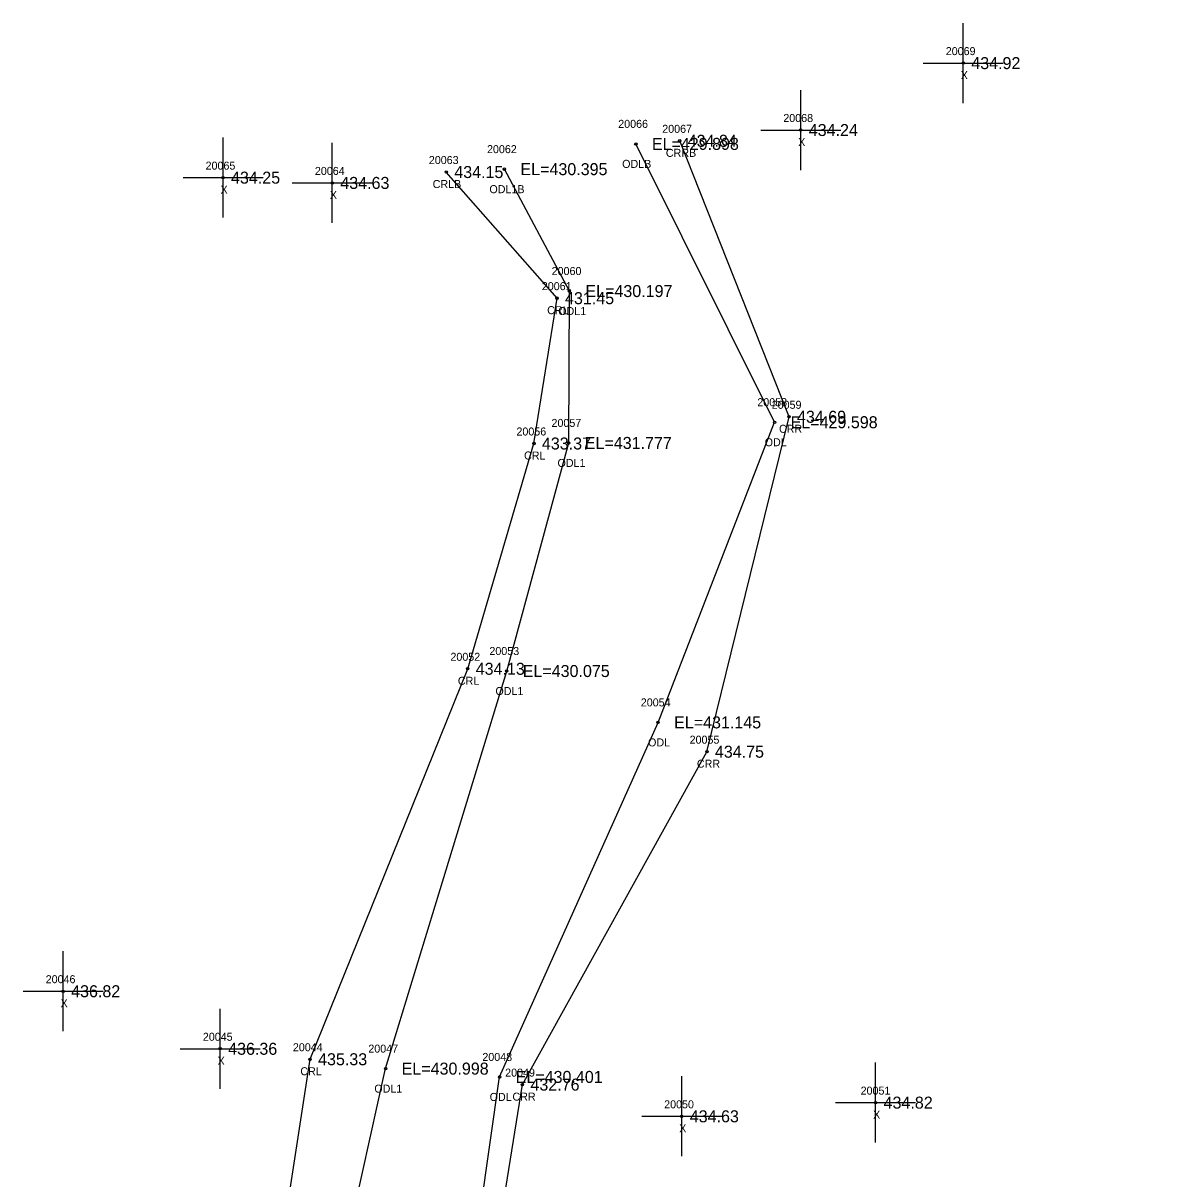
# Model space of a CAD drawing. Extents: x 1810114 to 1811498, y 790790 to 791824.
# Drawn here: x 1810690.3 to 1810832.5, y 791679.6 to 791824 of the extents above; entities that cross this region are included whole.
import ezdxf

# ---------------------------------------------------------------- set-up
doc = ezdxf.new("R2010")
doc.units = 0
for name, color, linetype in [('RD_EX_H2O', 7, 'Continuous'), ('RD_EX_H2O_txCode', 7, 'Continuous'), ('RD_EX_Misc', 7, 'Continuous'), ('RD_EX_Misc_txCode', 7, 'Continuous'), ('RD_EX_TX_H2O_ELEV', 7, 'Continuous'), ('RD_EX_TX_Misc_ELEV', 7, 'Continuous'), ('RD_SMD_Locator', 7, 'Continuous')]:
    doc.layers.add(name, color=color, linetype=linetype)

msp = doc.modelspace()

# ---------------------------------------------------------------- linework, layer by layer
at = {"layer": 'RD_EX_H2O'}
for points in [[(1810794.5, 791298.9), (1810828.59, 791424.04), (1810821.51, 791432.91), (1810774.54, 791452.98), (1810741.95, 791465.37), (1810743.78, 791497), (1810736.7, 791599.78), (1810749.88, 791692.36), (1810769.68, 791736.66), (1810784.24, 791774.17), (1810766.9, 791808.95)], [(1810797.71, 791296.87), (1810832.51, 791426.19), (1810824.93, 791438.48), (1810774.65, 791454.91), (1810754.82, 791471.31), (1810756.82, 791503.13), (1810738.07, 791600.2), (1810752.73, 791691.4), (1810775.78, 791733), (1810786.04, 791774.85), (1810772.38, 791809.33)], [(1810783.58, 791301.54), (1810809.42, 791415.43), (1810809.03, 791421.06), (1810765.94, 791440.4), (1810731.85, 791461.34), (1810727.54, 791486.73), (1810720.53, 791597.07), (1810716.45, 791606.79), (1810735.63, 791693.4), (1810750.76, 791743.08), (1810758.52, 791771.58), (1810758.6, 791790.56), (1810750.48, 791805.79)], [(1810781.61, 791303.43), (1810807.2, 791415.78), (1810808.22, 791420.49), (1810765.69, 791434.41), (1810731.68, 791459.26), (1810725.69, 791486.37), (1810718.09, 791596.36), (1810712.45, 791605.3), (1810726.19, 791694.57), (1810745.89, 791743.36), (1810754.16, 791771.51), (1810757.05, 791789.67), (1810743.21, 791805.43)]]:
    msp.add_lwpolyline(points, dxfattribs=at)
at = {"layer": 'RD_EX_Misc'}
for p, q in [((1810807.82, 791814.04), (1810807.82, 791824.04)), ((1810802.82, 791819.04), (1810812.82, 791819.04)), ((1810787.51, 791805.68), (1810787.51, 791815.68)), ((1810782.51, 791810.68), (1810792.51, 791810.68)), ((1810715.31, 791799.73), (1810715.31, 791809.73)), ((1810728.97, 791799.07), (1810728.97, 791809.07)), ((1810710.31, 791804.73), (1810720.31, 791804.73)), ((1810723.97, 791804.07), (1810733.97, 791804.07)), ((1810695.33, 791698.07), (1810695.33, 791708.07)), ((1810690.33, 791703.07), (1810700.33, 791703.07)), ((1810714.95, 791690.88), (1810714.95, 791700.88)), ((1810709.95, 791695.88), (1810719.95, 791695.88)), ((1810796.86, 791684.15), (1810796.86, 791694.15)), ((1810772.64, 791682.44), (1810772.64, 791692.44)), ((1810791.86, 791689.15), (1810801.86, 791689.15)), ((1810767.64, 791687.44), (1810777.64, 791687.44))]:
    msp.add_line(p, q, dxfattribs=at)
at = {"layer": 'RD_SMD_Locator'}
for centre in [(1810807.82, 791819.04), (1810787.51, 791810.68), (1810766.9, 791808.95), (1810772.38, 791809.33), (1810743.21, 791805.43), (1810750.48, 791805.79), (1810715.31, 791804.73), (1810728.97, 791804.07), (1810757.05, 791789.67), (1810758.6, 791790.56), (1810784.24, 791774.17), (1810786.04, 791774.85), (1810754.16, 791771.51), (1810758.52, 791771.58), (1810745.89, 791743.36), (1810750.76, 791743.08), (1810769.68, 791736.66), (1810775.78, 791733), (1810695.33, 791703.07), (1810714.95, 791695.88), (1810726.19, 791694.57), (1810735.63, 791693.4), (1810749.88, 791692.36), (1810752.73, 791691.4), (1810796.86, 791689.15), (1810772.64, 791687.44)]:
    msp.add_circle(centre, 0.15, dxfattribs=at)

# ---------------------------------------------------------------- texts
at = {"layer": 'RD_EX_H2O_txCode'}
for s, p in [('20066', (1810764.7, 791810.95)), ('20067', (1810770.2, 791810.33)), ('20062', (1810748.3, 791807.79)), ('CRRB', (1810770.65, 791807.33)), ('20063', (1810741.03, 791806.43)), ('ODLB', (1810765.19, 791805.95)), ('CRLB', (1810741.51, 791803.43)), ('ODL1B', (1810748.6, 791802.79)), ('20060', (1810756.38, 791792.56)), ('20061', (1810755.15, 791790.67)), ('CRL', (1810755.82, 791787.67)), ('ODL1', (1810757.2, 791787.56)), ('20058', (1810782.08, 791776.17)), ('20059', (1810783.88, 791775.85)), ('20057', (1810756.36, 791773.58)), ('CRR', (1810784.79, 791772.85)), ('20056', (1810751.98, 791772.51)), ('ODL', (1810783, 791771.17)), ('CRL', (1810752.93, 791769.51)), ('ODL1', (1810757.11, 791768.58)), ('20052', (1810743.73, 791744.36)), ('20053', (1810748.6, 791745.08)), ('CRL', (1810744.66, 791741.36)), ('ODL1', (1810749.35, 791740.08)), ('20054', (1810767.52, 791738.66)), ('ODL', (1810768.43, 791733.66)), ('20055', (1810773.62, 791734)), ('CRR', (1810774.53, 791731)), ('20044', (1810724.04, 791695.57)), ('20047', (1810733.47, 791695.4)), ('20048', (1810747.72, 791694.36)), ('CRL', (1810724.97, 791692.57)), ('20049', (1810750.57, 791692.4)), ('ODL1', (1810734.22, 791690.4)), ('ODL', (1810748.63, 791689.36)), ('CRR', (1810751.48, 791689.4))]:
    msp.add_text(s, height=1, dxfattribs=at).set_placement(p)
at = {"layer": 'RD_EX_Misc_txCode'}
for s, p in [('20069', (1810805.63, 791820.04)), ('X', (1810807.5, 791817.04)), ('20068', (1810785.33, 791811.68)), ('X', (1810787.19, 791808.68)), ('20065', (1810713.13, 791805.73)), ('20064', (1810726.79, 791805.07)), ('X', (1810715, 791802.73)), ('X', (1810728.66, 791802.07)), ('20046', (1810693.15, 791704.07)), ('X', (1810695.01, 791701.07)), ('20045', (1810712.79, 791696.88)), ('X', (1810714.63, 791693.88)), ('20051', (1810794.99, 791690.15)), ('20050', (1810770.44, 791688.44)), ('X', (1810796.55, 791687.15)), ('X', (1810772.32, 791685.44))]:
    msp.add_text(s, height=1, dxfattribs=at).set_placement(p)
at = {"layer": 'RD_EX_TX_H2O_ELEV'}
for s, p in [('434.84', (1810773.38, 791808.58)), ('EL=429.898', (1810768.9, 791808.2)), ('434.15', (1810744.21, 791804.68)), ('EL=430.395', (1810752.48, 791805.04)), ('EL=430.197', (1810760.6, 791789.81)), ('431.45', (1810758.05, 791788.92)), ('434.69', (1810787.04, 791774.1)), ('EL=429.598', (1810786.24, 791773.42)), ('433.37', (1810755.16, 791770.76)), ('EL=431.777', (1810760.52, 791770.83)), ('434.13', (1810746.89, 791742.61)), ('EL=430.075', (1810752.76, 791742.33)), ('EL=431.145', (1810771.68, 791735.91)), ('434.75', (1810776.78, 791732.25)), ('435.33', (1810727.19, 791693.82)), ('EL=430.998', (1810737.63, 791692.65)), ('EL=430.401', (1810751.88, 791691.61)), ('432.76', (1810753.73, 791690.65))]:
    msp.add_text(s, height=1.5, dxfattribs=at).set_placement(p)
at = {"layer": 'RD_EX_TX_Misc_ELEV'}
for s, p in [('434.92', (1810808.82, 791818.29)), ('434.24', (1810788.51, 791809.93)), ('434.25', (1810716.31, 791803.98)), ('434.63', (1810729.97, 791803.32)), ('436.82', (1810696.33, 791702.32)), ('436.36', (1810715.95, 791695.13)), ('434.82', (1810797.86, 791688.4)), ('434.63', (1810773.64, 791686.69))]:
    msp.add_text(s, height=1.5, dxfattribs=at).set_placement(p)

doc.saveas('drawing.dxf')
